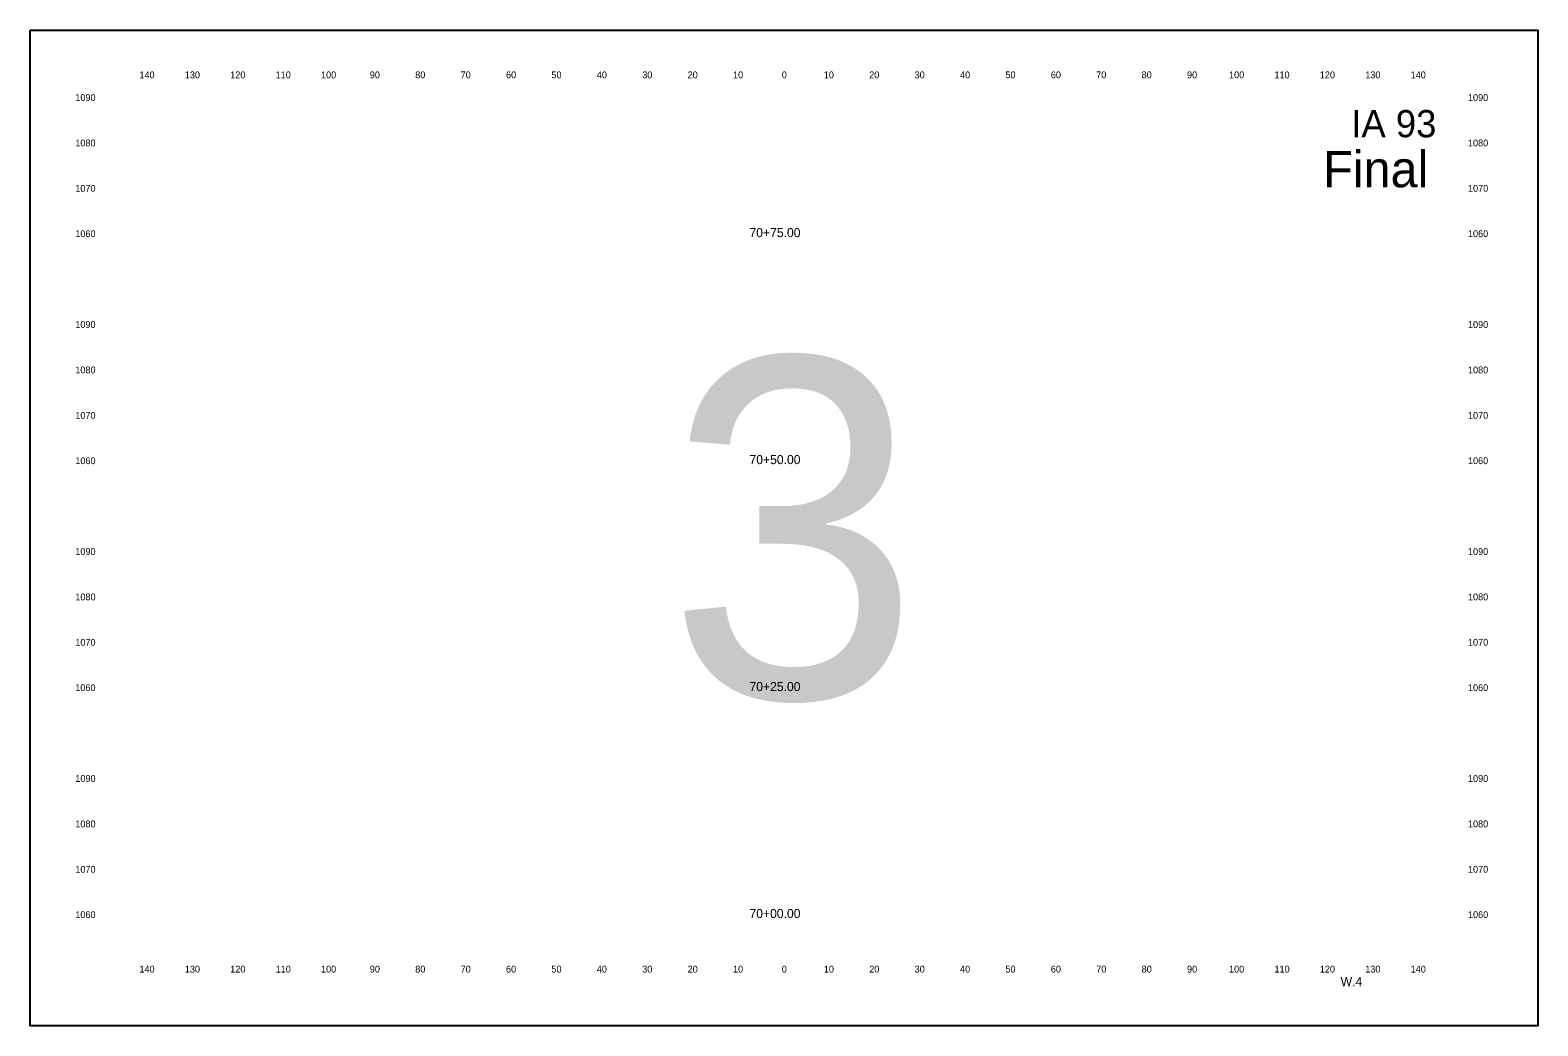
# Model space of a CAD drawing. Extents: x 10123 to 11535, y 9730 to 9950.
# Drawn here: x 10843.2 to 11175.3, y 9730.3 to 9949.6 of the extents above; entities that cross this region are included whole.
import ezdxf

# ---------------------------------------------------------------- set-up
doc = ezdxf.new("R2010")
doc.units = 0
for name, color, linetype in [('dsn3DSubgradeHingePoint', 7, 'Continuous'), ('dsnXSEarthwork', 7, 'Continuous'), ('dsnXsPCCPavement', 7, 'Continuous'), ('dsnXsShldrEarthFill', 7, 'Continuous')]:
    doc.layers.add(name, color=color, linetype=linetype)

msp = doc.modelspace()

# ---------------------------------------------------------------- linework, layer by layer
at = {"layer": 'dsnXsShldrEarthFill'}
msp.add_lwpolyline([(10843.21, 9949.6), (11175.29, 9949.6), (11175.29, 9730.26), (10843.21, 9730.26)], close=True, dxfattribs=at)

# ---------------------------------------------------------------- texts
at = {"layer": 'dsn3DSubgradeHingePoint'}
for s, height, p in [('140', 1.5, (10867.27, 9939)), ('130', 1.5, (10877.27, 9939)), ('120', 1.5, (10887.27, 9939)), ('110', 1.5, (10897.27, 9939)), ('100', 1.5, (10907.27, 9939)), ('90', 1.5, (10918.02, 9939)), ('80', 1.5, (10928.02, 9939)), ('70', 1.5, (10938.02, 9939)), ('60', 1.5, (10948.02, 9939)), ('50', 1.5, (10958.02, 9939)), ('40', 1.5, (10968.02, 9939)), ('30', 1.5, (10978.02, 9939)), ('20', 1.5, (10988.02, 9939)), ('10', 1.5, (10998.02, 9939)), ('0', 1.5, (11008.76, 9939)), ('0', 1.5, (11008.76, 9939)), ('10', 1.5, (11018.02, 9939)), ('20', 1.5, (11028.02, 9939)), ('30', 1.5, (11038.02, 9939)), ('40', 1.5, (11048.02, 9939)), ('50', 1.5, (11058.02, 9939)), ('60', 1.5, (11068.02, 9939)), ('70', 1.5, (11078.02, 9939)), ('80', 1.5, (11088.02, 9939)), ('90', 1.5, (11098.02, 9939)), ('100', 1.5, (11107.27, 9939)), ('110', 1.5, (11117.27, 9939)), ('120', 1.5, (11127.27, 9939)), ('130', 1.5, (11137.27, 9939)), ('140', 1.5, (11147.27, 9939)), ('1090', 1.5, (10853.15, 9934)), ('1090', 1.5, (11159.9, 9934)), ('IA 93', 6, (11134.21, 9926)), ('1080', 1.5, (10853.15, 9924)), ('1080', 1.5, (11159.9, 9924)), ('1070', 1.5, (10853.15, 9914)), ('1070', 1.5, (11159.9, 9914)), ('1060', 1.5, (10853.15, 9904)), ('70+75.00', 2, (11001.65, 9904)), ('1060', 1.5, (11159.9, 9904)), ('1090', 1.5, (10853.15, 9884)), ('1090', 1.5, (11159.9, 9884)), ('1080', 1.5, (10853.15, 9874)), ('1080', 1.5, (11159.9, 9874)), ('1070', 1.5, (10853.15, 9864)), ('1070', 1.5, (11159.9, 9864)), ('1060', 1.5, (10853.15, 9854)), ('70+50.00', 2, (11001.65, 9854)), ('1060', 1.5, (11159.9, 9854)), ('1090', 1.5, (10853.15, 9834)), ('1090', 1.5, (11159.9, 9834)), ('1080', 1.5, (10853.15, 9824)), ('1080', 1.5, (11159.9, 9824)), ('1070', 1.5, (10853.15, 9814)), ('1070', 1.5, (11159.9, 9814)), ('1060', 1.5, (10853.15, 9804)), ('70+25.00', 2, (11001.65, 9804)), ('1060', 1.5, (11159.9, 9804)), ('1090', 1.5, (10853.15, 9784)), ('1090', 1.5, (11159.9, 9784)), ('1080', 1.5, (10853.15, 9774)), ('1080', 1.5, (11159.9, 9774)), ('1070', 1.5, (10853.15, 9764)), ('1070', 1.5, (11159.9, 9764)), ('1060', 1.5, (10853.15, 9754)), ('70+00.00', 2, (11001.65, 9754)), ('1060', 1.5, (11159.9, 9754)), ('140', 1.5, (10867.27, 9742)), ('130', 1.5, (10877.27, 9742)), ('120', 1.5, (10887.27, 9742)), ('110', 1.5, (10897.27, 9742)), ('100', 1.5, (10907.27, 9742)), ('90', 1.5, (10918.02, 9742)), ('80', 1.5, (10928.02, 9742)), ('70', 1.5, (10938.02, 9742)), ('60', 1.5, (10948.02, 9742)), ('50', 1.5, (10958.02, 9742)), ('40', 1.5, (10968.02, 9742)), ('30', 1.5, (10978.02, 9742)), ('20', 1.5, (10988.02, 9742)), ('10', 1.5, (10998.02, 9742)), ('0', 1.5, (11008.76, 9742)), ('0', 1.5, (11008.76, 9742)), ('10', 1.5, (11018.02, 9742)), ('20', 1.5, (11028.02, 9742)), ('30', 1.5, (11038.02, 9742)), ('40', 1.5, (11048.02, 9742)), ('50', 1.5, (11058.02, 9742)), ('60', 1.5, (11068.02, 9742)), ('70', 1.5, (11078.02, 9742)), ('80', 1.5, (11088.02, 9742)), ('90', 1.5, (11098.02, 9742)), ('100', 1.5, (11107.27, 9742)), ('110', 1.5, (11117.27, 9742)), ('120', 1.5, (11127.27, 9742)), ('130', 1.5, (11137.27, 9742)), ('140', 1.5, (11147.27, 9742))]:
    msp.add_text(s, height=height, dxfattribs=at).set_placement(p)
at = {"layer": 'dsnXSEarthwork'}
msp.add_text('Final', height=8, dxfattribs=at).set_placement((11128, 9915))
at = {"layer": 'dsnXsPCCPavement'}
msp.add_text('W.4', height=2, dxfattribs=at).set_placement((11131.86, 9739))
at = {"layer": 'dsnXsShldrEarthFill'}
msp.add_text('3', height=75, dxfattribs=at).set_placement((10983.48, 9802.43))

doc.saveas('drawing.dxf')
